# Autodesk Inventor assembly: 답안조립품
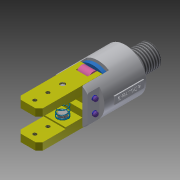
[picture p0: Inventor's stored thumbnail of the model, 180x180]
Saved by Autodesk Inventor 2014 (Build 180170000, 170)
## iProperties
Created: 2019-02
Part Number: 답안조립품
Document SubType Name: Assembly
Designer: OA55
Author: OA55
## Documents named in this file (11)
- C:\Users\OA55\Desktop\490208V1007\답안조립품.iam
- C:\Users\OA55\Desktop\490208V1007\본체.ipt
- C:\Users\OA55\Desktop\490208V1007\O-링.ipt
- C:\Users\OA55\Desktop\490208V1007\피스톤.ipt
- C:\Users\OA55\Desktop\490208V1007\핑거.ipt
- C:\Users\OA55\Desktop\490208V1007\부시.ipt
- C:\Users\OA55\Desktop\490208V1007\평행핀 6x28.ipt
- C:\Users\OA55\Desktop\490208V1007\핀.ipt
- C:\Users\OA55\Desktop\490208V1007\E-링.ipt
- C:\Users\OA55\Desktop\490208V1007\가이드핀.ipt
- C:\Users\OA55\Desktop\490208V1007\스프링.ipt
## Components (13 placed, 6 different names)
1. O-링:1
2. O-링:2
3. 피스톤:1
4. 핑거:1
5. 핑거:2 — 각도:1
6. 핀:1
7. 핀:2
8. E-링:1
9. E-링:2
10. E-링:3
11. E-링:4
12. 가이드핀:1
13. 가이드핀:2
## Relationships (1: Angle 1)
- 각도:1 [Angle]: 핑거:2
